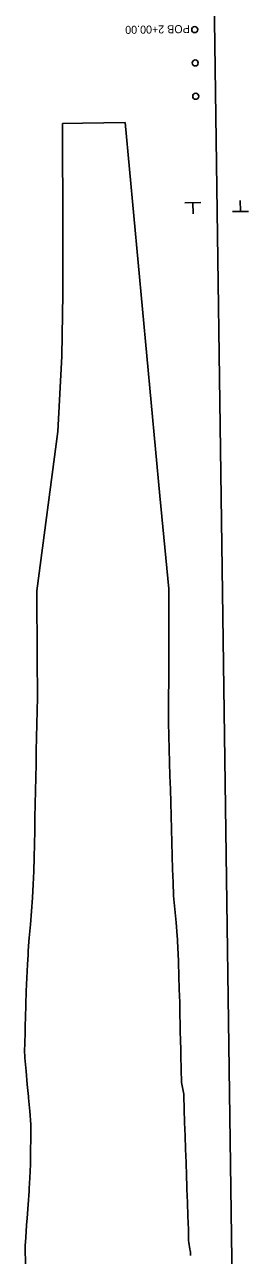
# Model space of a CAD drawing. Extents: x 1665984 to 1683035, y 227404 to 233856.
# Drawn here: x 1677303 to 1677471, y 229189 to 230111 of the extents above; entities that cross this region are included whole.
import ezdxf

# ---------------------------------------------------------------- set-up
doc = ezdxf.new("R2010")
doc.units = 0
for name, color, linetype in [('Default', 7, 'Continuous'), ('Level 47', 7, 'Continuous'), ('R_Draft', 7, 'Continuous'), ('R_Horz Alg Annot', 7, 'Continuous'), ('R_Striping', 7, 'Continuous')]:
    doc.layers.add(name, color=color, linetype=linetype)

msp = doc.modelspace()

# ---------------------------------------------------------------- linework, layer by layer
at = {"layer": 'Default'}
for p, q in [((1677435.14, 229977.92), (1677423.29, 229977.77)), ((1677429.25, 229977.67), (1677429.35, 229969.59)), ((1677464.91, 229971.42), (1677464.81, 229979.51)), ((1677459.02, 229971.17), (1677470.87, 229971.33))]:
    msp.add_line(p, q, dxfattribs=at)
at = {"layer": 'Level 47'}
for centre in [(1677430.63, 230107.58), (1677431, 230082.58), (1677431.36, 230057.58)]:
    msp.add_circle(centre, 2.25, dxfattribs=at)
at = {"layer": 'R_Draft'}
for p, q in [((1677346.5, 230037.44), (1677331.39, 230037.23)), ((1677378.37, 230037.89), (1677346.5, 230037.44))]:
    msp.add_line(p, q, dxfattribs=at)
for points in [[(1677331.39, 230037.23), (1677331.85, 229955.95), (1677331.75, 229909.6), (1677330.88, 229862.77), (1677328.06, 229806.45), (1677312.37, 229686.93)], [(1677427.06, 229193.49), (1677426.1, 229198.48), (1677426.07, 229200.03), (1677425.88, 229208.48), (1677425.77, 229213.02), (1677425.59, 229218.47), (1677425.21, 229228.47), (1677424.82, 229238.46), (1677424.74, 229240.61), (1677424.46, 229248.46), (1677424.12, 229258.46), (1677423.77, 229268.45), (1677423.38, 229278.45), (1677423, 229288.44), (1677422.7, 229298.44), (1677422.46, 229308.44), (1677422.43, 229309.58), (1677420.8, 229318.41), (1677420.55, 229328.41), (1677420.26, 229338.41), (1677420.12, 229344.48), (1677420.04, 229348.41), (1677419.83, 229358.4), (1677419.72, 229362.86), (1677419.59, 229368.4), (1677419.35, 229378.4), (1677419.06, 229388.4), (1677418.76, 229398.39), (1677418.44, 229408.39), (1677418.2, 229415.54), (1677418.09, 229418.39), (1677417.83, 229425.53), (1677417.58, 229428.38), (1677416.65, 229438.37), (1677415.72, 229448.36), (1677414.81, 229458.34), (1677414.79, 229458.49), (1677414.36, 229468.34), (1677414, 229478.33), (1677413.69, 229488.33), (1677413.49, 229498.33), (1677413.23, 229508.33), (1677412.94, 229518.32), (1677412.71, 229528.32), (1677412.35, 229538.32), (1677412.03, 229548.31), (1677411.76, 229558.31), (1677411.46, 229568.31), (1677411.18, 229578.3), (1677410.99, 229588.3), (1677411.04, 229598.3), (1677411.08, 229608.31), (1677411.17, 229618.31), (1677411.24, 229628.31), (1677411.31, 229638.31), (1677411.25, 229648.31), (1677411.21, 229658.31), (1677411.19, 229668.31), (1677411.16, 229678.31), (1677411.17, 229688.32), (1677404.47, 229758.23), (1677378.37, 230037.89)], [(1677312.37, 229686.93), (1677312.35, 229676.93), (1677312.36, 229666.92), (1677312.44, 229656.92), (1677312.5, 229646.92), (1677312.54, 229636.92), (1677312.6, 229626.92), (1677312.66, 229616.92), (1677312.7, 229606.92), (1677312.52, 229596.92), (1677312.3, 229586.92), (1677312.04, 229576.91), (1677311.82, 229566.91), (1677311.65, 229556.9), (1677311.43, 229546.9), (1677311.22, 229536.9), (1677311.03, 229526.89), (1677310.85, 229516.89), (1677310.66, 229506.88), (1677310.45, 229496.88), (1677310.21, 229486.88), (1677309.96, 229476.87), (1677309.52, 229466.86), (1677309.08, 229457.01), (1677309.07, 229456.86), (1677308.24, 229446.84), (1677307.4, 229436.83), (1677306.58, 229426.82), (1677306.33, 229423.96), (1677305.85, 229416.81), (1677305.71, 229413.96), (1677305.37, 229406.8), (1677304.79, 229396.79), (1677304.32, 229386.78), (1677303.93, 229376.78), (1677303.65, 229366.77), (1677303.61, 229361.23), (1677303.49, 229356.77), (1677303.16, 229346.76), (1677303.1, 229342.83), (1677303.28, 229336.76), (1677304.17, 229326.77), (1677305.07, 229316.79), (1677305.93, 229307.94), (1677306.05, 229306.8), (1677307.05, 229296.81), (1677307.87, 229286.82), (1677307.7, 229276.82), (1677307.57, 229266.82), (1677307.54, 229256.82), (1677307.11, 229246.81), (1677306.56, 229238.95), (1677306.39, 229236.8), (1677305.65, 229226.79), (1677304.92, 229216.77), (1677304.54, 229211.31), (1677304.24, 229206.76), (1677303.68, 229198.31), (1677303.46, 229196.75), (1677303.76, 229179.76)]]:
    msp.add_lwpolyline(points, dxfattribs=at)
msp.add_arc((1677401.9, 229188.68), 25.61, 0.15333, 10.82415, dxfattribs=at)
at = {"layer": 'R_Striping'}
msp.add_line((1677459.23, 229138.78), (1677443.59, 230250.71), dxfattribs=at)

# ---------------------------------------------------------------- texts
at = {"layer": 'R_Horz Alg Annot'}
msp.add_text('POB 2+00.00', height=6, rotation=180.80558, dxfattribs=at).set_placement((1677426.87, 230111.05))

doc.saveas('drawing.dxf')
